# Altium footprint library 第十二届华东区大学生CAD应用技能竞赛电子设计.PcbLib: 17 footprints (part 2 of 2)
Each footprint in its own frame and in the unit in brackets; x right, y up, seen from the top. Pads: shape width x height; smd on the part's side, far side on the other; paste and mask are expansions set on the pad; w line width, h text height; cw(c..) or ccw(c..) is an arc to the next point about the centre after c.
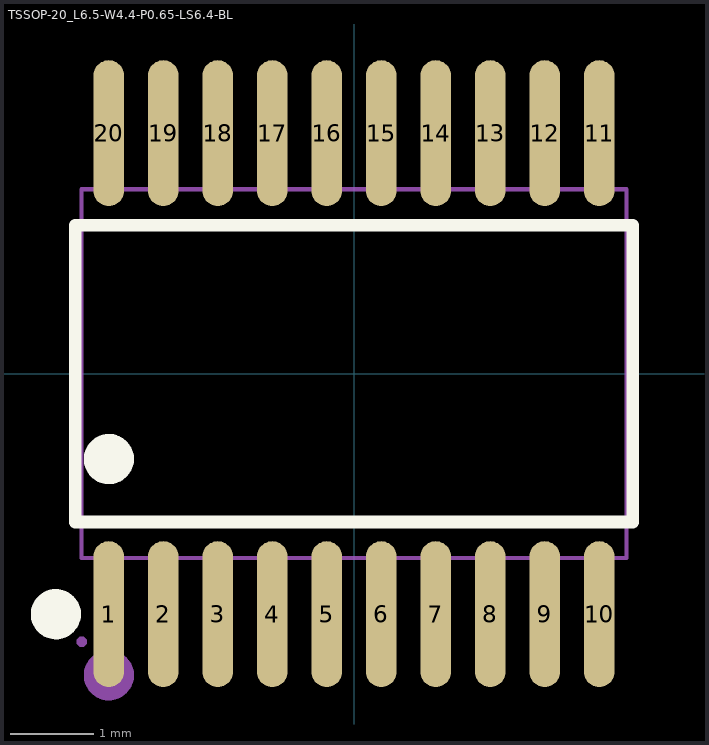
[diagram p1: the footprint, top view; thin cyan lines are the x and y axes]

## TSSOP-20_L6.5-W4.4-P0.65-LS6.4-BL [mil]
pads (20):
  oval 14.3x68.6 smd mask+2: 1(-115.2,-113) 2(-89.6,-113) 3(-64,-113) 4(-38.4,-113) 5(-12.8,-113) 6(12.8,-113) 7(38.4,-113) 8(64,-113) 9(89.6,-113) 10(115.2,-113) 11(115.2,113) 12(89.6,113) 13(64,113) 14(38.4,113) 15(12.8,113) 16(-12.8,113) 17(-38.4,113) 18(-64,113) 19(-89.6,113) 20(-115.2,113)
Top Overlay:
  circle w11.8: c-115.2,-40.1 r5.9
  circle w11.8: c-140.1,-113 r5.9
  lines w6: -131,-69.7 -131,69.7 131,69.7 131,-69.7 -131,-69.7
Mechanical 6:
  circle w11.8: c-115.2,-141.7 r5.9
Mechanical 15:
  drawing of 45 lines, arcs and shapes, not listed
